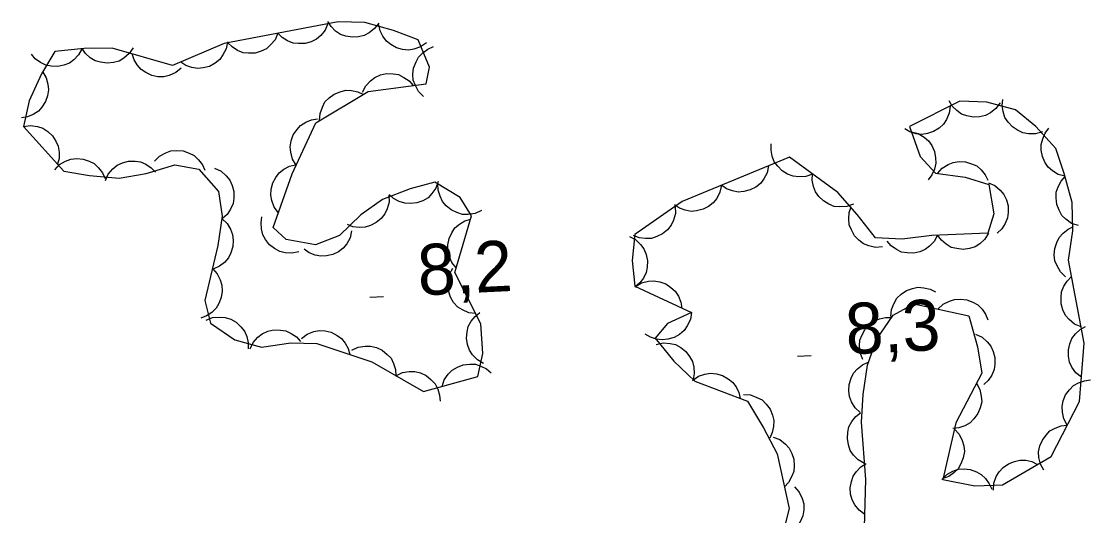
# Model space of a CAD drawing. Extents: x 336540 to 340074, y 5572036 to 5573747.
# Drawn here: x 337087.8 to 337150.7, y 5573228.9 to 5573258 of the extents above; entities that cross this region are included whole.
import ezdxf

# ---------------------------------------------------------------- set-up
doc = ezdxf.new("R2010")
doc.units = 0
doc.layers.add('Niveau 3', color=7, linetype='Continuous')
doc.layers.add('Niveau 44', color=7, linetype='Continuous')

msp = doc.modelspace()

# ---------------------------------------------------------------- linework, layer by layer
at = {"layer": 'Niveau 3'}
for p, q in [((337108.28, 5573241.8), (337109.08, 5573241.84)), ((337133.45, 5573238.33), (337134.25, 5573238.37))]:
    msp.add_line(p, q, dxfattribs=at)
at = {"layer": 'Niveau 44'}
for points in [[(337087.91, 5573251.86), (337090.28, 5573249.22), (337091.79, 5573248.96), (337093.53, 5573248.81), (337095.13, 5573249.08), (337096.8, 5573249.6), (337098.22, 5573249.34), (337099.37, 5573248.03), (337099.6, 5573246.58), (337099.33, 5573244.85), (337098.58, 5573241.6), (337098.9, 5573240.27), (337100.34, 5573239.29), (337101.91, 5573238.86), (337103.64, 5573239.11), (337105.17, 5573239.07), (337108.4, 5573237.99), (337111.44, 5573236.24), (337114.64, 5573237.12), (337114.93, 5573238.49), (337114.81, 5573240.23), (337113.29, 5573243.26), (337114.27, 5573246.59), (337113.6, 5573247.67), (337112.11, 5573248.57), (337110.66, 5573248.18), (337109.02, 5573247.55), (337107.76, 5573246.65), (337106.5, 5573245.43), (337105.08, 5573244.88), (337103.36, 5573245.19), (337102.6, 5573245.91), (337103.71, 5573249.06), (337105.1, 5573252.07), (337108.19, 5573253.92), (337111.59, 5573254.37), (337111.79, 5573255.36), (337111.12, 5573256.97), (337109.68, 5573257.52), (337107.99, 5573257.98), (337106.41, 5573258.03), (337099.71, 5573256.75), (337096.68, 5573255.44), (337093.13, 5573256.48), (337091.47, 5573256.46), (337089.74, 5573256.27), (337088.96, 5573254.96), (337088.24, 5573253.37), (337087.91, 5573251.86)], [(337108.81, 5573257.95), (337108.56, 5573257.62), (337108.24, 5573257.37), (337107.95, 5573257.21), (337107.61, 5573257.13), (337107.24, 5573257.11), (337106.86, 5573257.18), (337106.55, 5573257.28), (337106.26, 5573257.48), (337106, 5573257.74), (337105.81, 5573258.05)], [(337102.87, 5573257.35), (337102.71, 5573256.97), (337102.44, 5573256.66), (337102.2, 5573256.44), (337101.88, 5573256.29), (337101.53, 5573256.18), (337101.14, 5573256.18), (337100.82, 5573256.2), (337100.49, 5573256.34), (337100.18, 5573256.54), (337099.92, 5573256.79)], [(337105.82, 5573257.92), (337105.65, 5573257.53), (337105.39, 5573257.22), (337105.15, 5573257), (337104.83, 5573256.85), (337104.47, 5573256.75), (337104.09, 5573256.74), (337103.77, 5573256.77), (337103.44, 5573256.9), (337103.13, 5573257.1), (337102.87, 5573257.35)], [(337111.61, 5573256.78), (337111.27, 5573256.54), (337110.88, 5573256.42), (337110.56, 5573256.36), (337110.21, 5573256.39), (337109.85, 5573256.5), (337109.52, 5573256.69), (337109.26, 5573256.88), (337109.05, 5573257.17), (337108.89, 5573257.5), (337108.81, 5573257.85)], [(337099.91, 5573256.84), (337099.83, 5573256.43), (337099.64, 5573256.07), (337099.45, 5573255.8), (337099.18, 5573255.58), (337098.85, 5573255.4), (337098.48, 5573255.31), (337098.16, 5573255.27), (337097.81, 5573255.33), (337097.46, 5573255.45), (337097.16, 5573255.65)], [(337091.35, 5573256.45), (337091.15, 5573256.08), (337090.87, 5573255.79), (337090.61, 5573255.59), (337090.28, 5573255.46), (337089.92, 5573255.39), (337089.53, 5573255.41), (337089.21, 5573255.46), (337088.9, 5573255.62), (337088.6, 5573255.85), (337088.37, 5573256.12)], [(337094.35, 5573256.49), (337094.12, 5573256.15), (337093.81, 5573255.89), (337093.53, 5573255.71), (337093.19, 5573255.62), (337092.82, 5573255.58), (337092.44, 5573255.64), (337092.13, 5573255.72), (337091.83, 5573255.91), (337091.55, 5573256.16), (337091.35, 5573256.46)], [(337097.18, 5573255.29), (337096.86, 5573255.03), (337096.48, 5573254.87), (337096.16, 5573254.79), (337095.81, 5573254.79), (337095.45, 5573254.87), (337095.1, 5573255.03), (337094.83, 5573255.21), (337094.6, 5573255.48), (337094.41, 5573255.79), (337094.3, 5573256.14)], [(337111.44, 5573253.62), (337111.14, 5573253.91), (337110.96, 5573254.27), (337110.84, 5573254.58), (337110.82, 5573254.94), (337110.86, 5573255.3), (337111, 5573255.66), (337111.15, 5573255.95), (337111.4, 5573256.2), (337111.7, 5573256.42), (337112.03, 5573256.56)], [(337089.02, 5573255.09), (337089.24, 5573254.73), (337089.34, 5573254.34), (337089.38, 5573254.01), (337089.32, 5573253.67), (337089.2, 5573253.32), (337088.99, 5573253), (337088.78, 5573252.75), (337088.48, 5573252.56), (337088.14, 5573252.42), (337087.78, 5573252.36)], [(337107.85, 5573253.88), (337108.04, 5573254.25), (337108.32, 5573254.54), (337108.58, 5573254.75), (337108.9, 5573254.89), (337109.26, 5573254.97), (337109.65, 5573254.95), (337109.97, 5573254.91), (337110.29, 5573254.75), (337110.59, 5573254.54), (337110.83, 5573254.27)], [(337105.32, 5573252.2), (337105.35, 5573252.62), (337105.49, 5573253), (337105.64, 5573253.3), (337105.89, 5573253.55), (337106.19, 5573253.76), (337106.54, 5573253.9), (337106.86, 5573253.99), (337107.21, 5573253.97), (337107.57, 5573253.9), (337107.9, 5573253.75)], [(337137.37, 5573227.55), (337137.46, 5573231.05), (337137.2, 5573234.44), (337137.3, 5573236.06), (337137.57, 5573237.79), (337138.09, 5573239.3), (337139.08, 5573240.74), (337140.28, 5573241.4), (337143.53, 5573240.7), (337144.04, 5573238.87), (337144.29, 5573237.33), (337142.76, 5573234.4), (337141.99, 5573231.05), (337143.87, 5573230.68), (337145.5, 5573230.74), (337148.36, 5573232.42), (337150.03, 5573235.65), (337150.31, 5573239.1), (337149.38, 5573243.99), (337149.65, 5573245.71), (337149.6, 5573247.38), (337149.14, 5573249.08), (337148.64, 5573250.56), (337147.47, 5573251.86), (337146.27, 5573252.84), (337144.58, 5573253.28), (337143, 5573253.34), (337140.04, 5573251.86), (337140.66, 5573250.09), (337141.57, 5573249.1), (337143.3, 5573248.87), (337144.7, 5573248.44), (337145, 5573246.72), (337144.64, 5573245.57), (337141.34, 5573245.43), (337139.6, 5573245.21), (337138.04, 5573245.29), (337136.96, 5573246.67), (337135.81, 5573247.96), (337132.98, 5573250.04), (337126.66, 5573247.44), (337123.88, 5573245.49), (337123.71, 5573243.97), (337123.88, 5573242.44), (337127.21, 5573240.89)], [(337142.43, 5573253.05), (337142.37, 5573252.64), (337142.21, 5573252.27), (337142.03, 5573251.99), (337141.77, 5573251.76), (337141.45, 5573251.56), (337141.09, 5573251.45), (337140.77, 5573251.39), (337140.42, 5573251.43), (337140.06, 5573251.54), (337139.75, 5573251.71)], [(337145.36, 5573253.25), (337145.11, 5573252.91), (337144.79, 5573252.67), (337144.5, 5573252.51), (337144.16, 5573252.43), (337143.79, 5573252.41), (337143.41, 5573252.49), (337143.1, 5573252.59), (337142.81, 5573252.8), (337142.55, 5573253.06), (337142.36, 5573253.36)], [(337147.85, 5573251.55), (337147.45, 5573251.43), (337147.04, 5573251.43), (337146.71, 5573251.48), (337146.39, 5573251.63), (337146.09, 5573251.83), (337145.83, 5573252.12), (337145.65, 5573252.39), (337145.54, 5573252.73), (337145.49, 5573253.09), (337145.52, 5573253.45)], [(337103.95, 5573249.58), (337103.74, 5573249.94), (337103.64, 5573250.34), (337103.6, 5573250.66), (337103.66, 5573251.01), (337103.78, 5573251.36), (337104, 5573251.67), (337104.21, 5573251.92), (337104.51, 5573252.11), (337104.85, 5573252.25), (337105.21, 5573252.31)], [(337087.91, 5573251.86), (337088.32, 5573251.92), (337088.73, 5573251.85), (337089.04, 5573251.76), (337089.34, 5573251.57), (337089.61, 5573251.31), (337089.81, 5573250.99), (337089.95, 5573250.7), (337090.01, 5573250.35), (337090, 5573249.98), (337089.91, 5573249.63)], [(337149.2, 5573248.92), (337148.79, 5573249.03), (337148.45, 5573249.24), (337148.2, 5573249.46), (337148, 5573249.75), (337147.85, 5573250.09), (337147.79, 5573250.47), (337147.78, 5573250.79), (337147.87, 5573251.13), (337148.02, 5573251.47), (337148.24, 5573251.76)], [(337140.15, 5573251.55), (337140.55, 5573251.44), (337140.9, 5573251.23), (337141.15, 5573251.02), (337141.35, 5573250.73), (337141.5, 5573250.39), (337141.57, 5573250.01), (337141.59, 5573249.69), (337141.5, 5573249.35), (337141.35, 5573249.01), (337141.14, 5573248.72)], [(337095.62, 5573249.82), (337095.91, 5573250.11), (337096.27, 5573250.31), (337096.58, 5573250.43), (337096.93, 5573250.45), (337097.3, 5573250.42), (337097.66, 5573250.29), (337097.95, 5573250.15), (337098.21, 5573249.9), (337098.43, 5573249.6), (337098.57, 5573249.28)], [(337134.32, 5573249.05), (337133.93, 5573248.91), (337133.52, 5573248.9), (337133.19, 5573248.92), (337132.86, 5573249.05), (337132.55, 5573249.24), (337132.28, 5573249.52), (337132.08, 5573249.78), (337131.96, 5573250.11), (337131.89, 5573250.47), (337131.9, 5573250.83)], [(337089.74, 5573249.31), (337090.03, 5573249.61), (337090.38, 5573249.81), (337090.69, 5573249.93), (337091.04, 5573249.97), (337091.41, 5573249.93), (337091.77, 5573249.81), (337092.07, 5573249.67), (337092.32, 5573249.43), (337092.55, 5573249.13), (337092.7, 5573248.8)], [(337092.72, 5573248.67), (337092.89, 5573249.05), (337093.16, 5573249.36), (337093.41, 5573249.57), (337093.73, 5573249.72), (337094.08, 5573249.81), (337094.47, 5573249.81), (337094.79, 5573249.78), (337095.11, 5573249.64), (337095.42, 5573249.43), (337095.67, 5573249.17)], [(337141.68, 5573249.09), (337141.96, 5573249.4), (337142.3, 5573249.61), (337142.6, 5573249.74), (337142.95, 5573249.79), (337143.32, 5573249.77), (337143.69, 5573249.66), (337143.99, 5573249.53), (337144.25, 5573249.3), (337144.49, 5573249.01), (337144.65, 5573248.69)], [(337099.15, 5573249.4), (337099.53, 5573249.22), (337099.83, 5573248.95), (337100.05, 5573248.7), (337100.19, 5573248.38), (337100.28, 5573248.02), (337100.28, 5573247.63), (337100.24, 5573247.31), (337100.09, 5573246.99), (337099.89, 5573246.68), (337099.62, 5573246.43)], [(337102.9, 5573246.77), (337102.66, 5573247.11), (337102.52, 5573247.49), (337102.45, 5573247.82), (337102.48, 5573248.17), (337102.57, 5573248.53), (337102.76, 5573248.86), (337102.94, 5573249.13), (337103.23, 5573249.34), (337103.55, 5573249.51), (337103.9, 5573249.6)], [(337131.74, 5573249.53), (337131.66, 5573249.12), (337131.46, 5573248.77), (337131.27, 5573248.5), (337130.99, 5573248.29), (337130.66, 5573248.12), (337130.29, 5573248.03), (337129.96, 5573247.99), (337129.62, 5573248.06), (337129.27, 5573248.19), (337128.97, 5573248.39)], [(337112.31, 5573248.62), (337112.17, 5573248.23), (337111.93, 5573247.9), (337111.71, 5573247.66), (337111.4, 5573247.48), (337111.05, 5573247.36), (337110.67, 5573247.32), (337110.35, 5573247.33), (337110.01, 5573247.44), (337109.68, 5573247.61), (337109.41, 5573247.84)], [(337136.74, 5573247.28), (337136.34, 5573247.14), (337135.94, 5573247.12), (337135.61, 5573247.15), (337135.28, 5573247.28), (337134.97, 5573247.47), (337134.7, 5573247.74), (337134.5, 5573248), (337134.38, 5573248.33), (337134.31, 5573248.7), (337134.32, 5573249.05)], [(337144.68, 5573248.54), (337145.06, 5573248.37), (337145.37, 5573248.1), (337145.59, 5573247.85), (337145.74, 5573247.53), (337145.83, 5573247.18), (337145.83, 5573246.79), (337145.8, 5573246.47), (337145.66, 5573246.15), (337145.46, 5573245.83), (337145.2, 5573245.58)], [(337149.97, 5573246.02), (337149.57, 5573246.15), (337149.24, 5573246.39), (337149, 5573246.62), (337148.83, 5573246.92), (337148.7, 5573247.27), (337148.66, 5573247.65), (337148.67, 5573247.98), (337148.78, 5573248.31), (337148.95, 5573248.64), (337149.19, 5573248.91)], [(337114.85, 5573246.91), (337114.47, 5573246.74), (337114.07, 5573246.68), (337113.74, 5573246.68), (337113.4, 5573246.78), (337113.07, 5573246.94), (337112.78, 5573247.19), (337112.56, 5573247.43), (337112.41, 5573247.75), (337112.3, 5573248.1), (337112.29, 5573248.46)], [(337128.97, 5573248.39), (337128.88, 5573247.98), (337128.69, 5573247.62), (337128.49, 5573247.36), (337128.21, 5573247.15), (337127.89, 5573246.98), (337127.51, 5573246.89), (337127.19, 5573246.85), (337126.84, 5573246.92), (337126.5, 5573247.05), (337126.2, 5573247.25)], [(337109.4, 5573247.82), (337109.41, 5573247.4), (337109.3, 5573247.01), (337109.17, 5573246.71), (337108.95, 5573246.44), (337108.66, 5573246.2), (337108.32, 5573246.03), (337108.01, 5573245.92), (337107.66, 5573245.9), (337107.29, 5573245.95), (337106.96, 5573246.08)], [(337126.25, 5573247.15), (337126.26, 5573246.73), (337126.14, 5573246.34), (337126.01, 5573246.04), (337125.79, 5573245.77), (337125.5, 5573245.53), (337125.16, 5573245.37), (337124.85, 5573245.26), (337124.5, 5573245.25), (337124.13, 5573245.3), (337123.79, 5573245.43)], [(337138.45, 5573244.76), (337138.04, 5573244.73), (337137.64, 5573244.82), (337137.33, 5573244.94), (337137.05, 5573245.15), (337136.8, 5573245.42), (337136.62, 5573245.76), (337136.49, 5573246.06), (337136.46, 5573246.41), (337136.49, 5573246.78), (337136.6, 5573247.12)], [(337099.58, 5573246.43), (337099.88, 5573246.15), (337100.09, 5573245.8), (337100.21, 5573245.49), (337100.25, 5573245.14), (337100.23, 5573244.78), (337100.1, 5573244.41), (337099.97, 5573244.11), (337099.73, 5573243.85), (337099.44, 5573243.62), (337099.11, 5573243.47)], [(337104.11, 5573244.48), (337103.7, 5573244.39), (337103.3, 5573244.42), (337102.98, 5573244.49), (337102.67, 5573244.66), (337102.38, 5573244.89), (337102.15, 5573245.19), (337101.98, 5573245.47), (337101.9, 5573245.82), (337101.88, 5573246.19), (337101.93, 5573246.54)], [(337113.37, 5573243.53), (337113.1, 5573243.85), (337112.95, 5573244.22), (337112.86, 5573244.54), (337112.87, 5573244.89), (337112.94, 5573245.26), (337113.11, 5573245.6), (337113.28, 5573245.88), (337113.55, 5573246.11), (337113.87, 5573246.29), (337114.22, 5573246.4)], [(337149.22, 5573243), (337148.92, 5573243.29), (337148.72, 5573243.64), (337148.59, 5573243.94), (337148.55, 5573244.29), (337148.58, 5573244.66), (337148.7, 5573245.03), (337148.84, 5573245.32), (337149.07, 5573245.58), (337149.36, 5573245.81), (337149.69, 5573245.97)], [(337107.21, 5573245.71), (337107.12, 5573245.3), (337106.92, 5573244.95), (337106.72, 5573244.68), (337106.43, 5573244.48), (337106.1, 5573244.31), (337105.73, 5573244.24), (337105.4, 5573244.21), (337105.06, 5573244.28), (337104.71, 5573244.42), (337104.42, 5573244.62)], [(337123.55, 5573245.38), (337123.92, 5573245.19), (337124.21, 5573244.9), (337124.41, 5573244.64), (337124.54, 5573244.31), (337124.61, 5573243.95), (337124.59, 5573243.57), (337124.54, 5573243.25), (337124.38, 5573242.93), (337124.16, 5573242.64), (337123.88, 5573242.4)], [(337141.69, 5573245.47), (337141.5, 5573245.1), (337141.22, 5573244.81), (337140.96, 5573244.6), (337140.64, 5573244.47), (337140.28, 5573244.39), (337139.89, 5573244.41), (337139.57, 5573244.46), (337139.26, 5573244.61), (337138.95, 5573244.83), (337138.72, 5573245.1)], [(337144.69, 5573245.57), (337144.47, 5573245.22), (337144.17, 5573244.95), (337143.89, 5573244.76), (337143.56, 5573244.66), (337143.19, 5573244.61), (337142.81, 5573244.66), (337142.49, 5573244.73), (337142.19, 5573244.92), (337141.91, 5573245.16), (337141.69, 5573245.45)], [(337099.02, 5573243.49), (337099.3, 5573243.18), (337099.48, 5573242.82), (337099.58, 5573242.5), (337099.59, 5573242.15), (337099.54, 5573241.79), (337099.4, 5573241.43), (337099.24, 5573241.15), (337098.98, 5573240.9), (337098.68, 5573240.7), (337098.34, 5573240.57)], [(337114.51, 5573240.83), (337114.1, 5573240.88), (337113.73, 5573241.05), (337113.45, 5573241.22), (337113.21, 5573241.49), (337113.02, 5573241.8), (337112.91, 5573242.17), (337112.84, 5573242.49), (337112.89, 5573242.84), (337112.99, 5573243.19), (337113.17, 5573243.51)], [(337150.13, 5573240.06), (337149.74, 5573240.22), (337149.43, 5573240.49), (337149.21, 5573240.73), (337149.06, 5573241.05), (337148.96, 5573241.41), (337148.95, 5573241.79), (337148.98, 5573242.11), (337149.12, 5573242.44), (337149.31, 5573242.75), (337149.57, 5573243.01)], [(337123.91, 5573242.42), (337124.27, 5573242.64), (337124.67, 5573242.74), (337125, 5573242.77), (337125.34, 5573242.71), (337125.69, 5573242.59), (337126, 5573242.37), (337126.25, 5573242.16), (337126.44, 5573241.86), (337126.58, 5573241.51), (337126.63, 5573241.16)], [(337138.94, 5573240.66), (337138.97, 5573241.08), (337139.13, 5573241.45), (337139.29, 5573241.74), (337139.55, 5573241.98), (337139.85, 5573242.19), (337140.22, 5573242.31), (337140.53, 5573242.39), (337140.88, 5573242.36), (337141.24, 5573242.27), (337141.56, 5573242.11)], [(337141.71, 5573241.09), (337142.01, 5573241.38), (337142.38, 5573241.56), (337142.69, 5573241.67), (337143.04, 5573241.69), (337143.41, 5573241.64), (337143.76, 5573241.5), (337144.05, 5573241.35), (337144.3, 5573241.1), (337144.51, 5573240.79), (337144.65, 5573240.46)], [(337098.65, 5573240.44), (337099.03, 5573240.6), (337099.44, 5573240.63), (337099.77, 5573240.61), (337100.1, 5573240.5), (337100.42, 5573240.32), (337100.7, 5573240.05), (337100.91, 5573239.8), (337101.04, 5573239.48), (337101.13, 5573239.12), (337101.13, 5573238.76)], [(337114.97, 5573237.9), (337114.61, 5573238.11), (337114.33, 5573238.41), (337114.14, 5573238.68), (337114.03, 5573239.01), (337113.97, 5573239.38), (337114.01, 5573239.76), (337114.07, 5573240.08), (337114.25, 5573240.39), (337114.48, 5573240.67), (337114.76, 5573240.9)], [(337127.21, 5573240.89), (337127.14, 5573240.48), (337126.96, 5573240.11), (337126.78, 5573239.84), (337126.51, 5573239.61), (337126.19, 5573239.43), (337125.82, 5573239.33), (337125.49, 5573239.28), (337125.15, 5573239.33), (337124.79, 5573239.45), (337124.49, 5573239.63)], [(337127.21, 5573240.89), (337125.8, 5573240.24), (337125.06, 5573239.38), (337126.17, 5573238.03), (337127.4, 5573236.85), (337130.5, 5573235.67), (337131.44, 5573234.11), (337132.24, 5573232.57), (337132.95, 5573229.36), (337132.1, 5573225.96)], [(337137.29, 5573238.13), (337137.13, 5573238.52), (337137.1, 5573238.93), (337137.12, 5573239.26), (337137.24, 5573239.59), (337137.42, 5573239.91), (337137.69, 5573240.18), (337137.94, 5573240.39), (337138.26, 5573240.53), (337138.63, 5573240.61), (337138.99, 5573240.6)], [(337101.24, 5573238.76), (337101.42, 5573239.14), (337101.7, 5573239.44), (337101.95, 5573239.65), (337102.28, 5573239.79), (337102.64, 5573239.87), (337103.02, 5573239.86), (337103.34, 5573239.82), (337103.66, 5573239.67), (337103.97, 5573239.46), (337104.21, 5573239.19)], [(337104.26, 5573239.37), (337104.6, 5573239.63), (337104.98, 5573239.77), (337105.3, 5573239.84), (337105.65, 5573239.82), (337106.01, 5573239.73), (337106.35, 5573239.55), (337106.62, 5573239.37), (337106.83, 5573239.09), (337107.01, 5573238.77), (337107.11, 5573238.42)], [(337150.15, 5573237.08), (337149.82, 5573237.34), (337149.59, 5573237.68), (337149.44, 5573237.98), (337149.38, 5573238.32), (337149.38, 5573238.69), (337149.47, 5573239.06), (337149.59, 5573239.37), (337149.8, 5573239.65), (337150.08, 5573239.9), (337150.39, 5573240.07)], [(337125.13, 5573239.02), (337125.54, 5573239.11), (337125.95, 5573239.08), (337126.27, 5573239.01), (337126.58, 5573238.84), (337126.87, 5573238.6), (337127.09, 5573238.3), (337127.26, 5573238.02), (337127.34, 5573237.67), (337127.36, 5573237.3), (337127.3, 5573236.95)], [(337143.92, 5573239.62), (337144.3, 5573239.44), (337144.6, 5573239.17), (337144.82, 5573238.92), (337144.96, 5573238.6), (337145.05, 5573238.24), (337145.05, 5573237.86), (337145.01, 5573237.53), (337144.87, 5573237.21), (337144.66, 5573236.9), (337144.4, 5573236.66)], [(337107.22, 5573238.67), (337107.6, 5573238.85), (337108, 5573238.92), (337108.33, 5573238.92), (337108.67, 5573238.83), (337109, 5573238.68), (337109.3, 5573238.43), (337109.53, 5573238.2), (337109.68, 5573237.89), (337109.79, 5573237.53), (337109.82, 5573237.17)], [(337112.53, 5573236.54), (337112.66, 5573236.94), (337112.9, 5573237.27), (337113.13, 5573237.51), (337113.43, 5573237.68), (337113.78, 5573237.81), (337114.16, 5573237.85), (337114.49, 5573237.85), (337114.82, 5573237.74), (337115.15, 5573237.57), (337115.42, 5573237.34)], [(337137.14, 5573235), (337136.83, 5573235.29), (337136.63, 5573235.64), (337136.5, 5573235.94), (337136.46, 5573236.29), (337136.49, 5573236.66), (337136.61, 5573237.03), (337136.74, 5573237.32), (337136.98, 5573237.58), (337137.27, 5573237.81), (337137.6, 5573237.97)], [(337109.82, 5573237.17), (337110.2, 5573237.36), (337110.6, 5573237.42), (337110.93, 5573237.43), (337111.27, 5573237.34), (337111.6, 5573237.18), (337111.9, 5573236.94), (337112.13, 5573236.7), (337112.28, 5573236.39), (337112.39, 5573236.03), (337112.42, 5573235.68)], [(337127.27, 5573236.9), (337127.61, 5573237.14), (337128, 5573237.27), (337128.32, 5573237.33), (337128.67, 5573237.29), (337129.03, 5573237.19), (337129.36, 5573236.99), (337129.62, 5573236.8), (337129.83, 5573236.51), (337129.99, 5573236.18), (337130.07, 5573235.83)], [(337143.97, 5573236.73), (337144.17, 5573236.36), (337144.25, 5573235.96), (337144.28, 5573235.63), (337144.2, 5573235.29), (337144.06, 5573234.95), (337143.82, 5573234.64), (337143.6, 5573234.4), (337143.29, 5573234.23), (337142.94, 5573234.11), (337142.59, 5573234.07)], [(337149.31, 5573234.26), (337149.11, 5573234.63), (337149.03, 5573235.03), (337149.01, 5573235.36), (337149.08, 5573235.7), (337149.22, 5573236.04), (337149.45, 5573236.35), (337149.68, 5573236.59), (337149.98, 5573236.76), (337150.33, 5573236.88), (337150.69, 5573236.93)], [(337130.26, 5573236.06), (337130.68, 5573236.04), (337131.06, 5573235.9), (337131.36, 5573235.75), (337131.61, 5573235.5), (337131.83, 5573235.2), (337131.97, 5573234.85), (337132.05, 5573234.53), (337132.04, 5573234.18), (337131.96, 5573233.82), (337131.81, 5573233.49)], [(337137.39, 5573232), (337137.02, 5573232.21), (337136.74, 5573232.5), (337136.55, 5573232.77), (337136.44, 5573233.1), (337136.38, 5573233.47), (337136.41, 5573233.85), (337136.47, 5573234.17), (337136.65, 5573234.48), (337136.88, 5573234.77), (337137.16, 5573234.99)], [(337142.68, 5573234.03), (337142.96, 5573233.73), (337143.14, 5573233.36), (337143.24, 5573233.05), (337143.26, 5573232.7), (337143.2, 5573232.33), (337143.06, 5573231.98), (337142.9, 5573231.69), (337142.65, 5573231.45), (337142.34, 5573231.24), (337142, 5573231.11)], [(337147.93, 5573231.6), (337147.74, 5573231.96), (337147.65, 5573232.36), (337147.63, 5573232.69), (337147.71, 5573233.04), (337147.85, 5573233.38), (337148.08, 5573233.68), (337148.3, 5573233.92), (337148.61, 5573234.09), (337148.96, 5573234.22), (337149.31, 5573234.26)], [(337132.02, 5573233.56), (337132.41, 5573233.41), (337132.73, 5573233.15), (337132.96, 5573232.91), (337133.12, 5573232.6), (337133.23, 5573232.25), (337133.25, 5573231.87), (337133.23, 5573231.54), (337133.1, 5573231.21), (337132.92, 5573230.89), (337132.67, 5573230.63)], [(337144.98, 5573230.43), (337145, 5573230.85), (337145.14, 5573231.23), (337145.3, 5573231.52), (337145.55, 5573231.77), (337145.85, 5573231.98), (337146.21, 5573232.12), (337146.52, 5573232.2), (337146.87, 5573232.19), (337147.24, 5573232.11), (337147.56, 5573231.95)], [(337137.41, 5573229), (337137.07, 5573229.25), (337136.82, 5573229.57), (337136.66, 5573229.86), (337136.57, 5573230.2), (337136.55, 5573230.57), (337136.62, 5573230.94), (337136.72, 5573231.25), (337136.92, 5573231.54), (337137.18, 5573231.81), (337137.48, 5573232)], [(337141.93, 5573231.06), (337142.23, 5573231.36), (337142.59, 5573231.55), (337142.9, 5573231.66), (337143.25, 5573231.68), (337143.61, 5573231.64), (337143.97, 5573231.51), (337144.26, 5573231.36), (337144.51, 5573231.11), (337144.73, 5573230.81), (337144.87, 5573230.48)], [(337133.27, 5573230.62), (337133.54, 5573230.31), (337133.72, 5573229.94), (337133.81, 5573229.63), (337133.82, 5573229.28), (337133.76, 5573228.91), (337133.61, 5573228.56), (337133.45, 5573228.28), (337133.19, 5573228.04), (337132.88, 5573227.84), (337132.54, 5573227.71)]]:
    msp.add_lwpolyline(points, dxfattribs=at)

# ---------------------------------------------------------------- texts
at = {"layer": 'Niveau 3'}
for s, p in [('8,2    ', (337111.16, 5573241.9)), ('8,3    ', (337136.33, 5573238.43))]:
    msp.add_text(s, height=3, rotation=2.7712, dxfattribs=at).set_placement(p)

doc.saveas('drawing.dxf')
